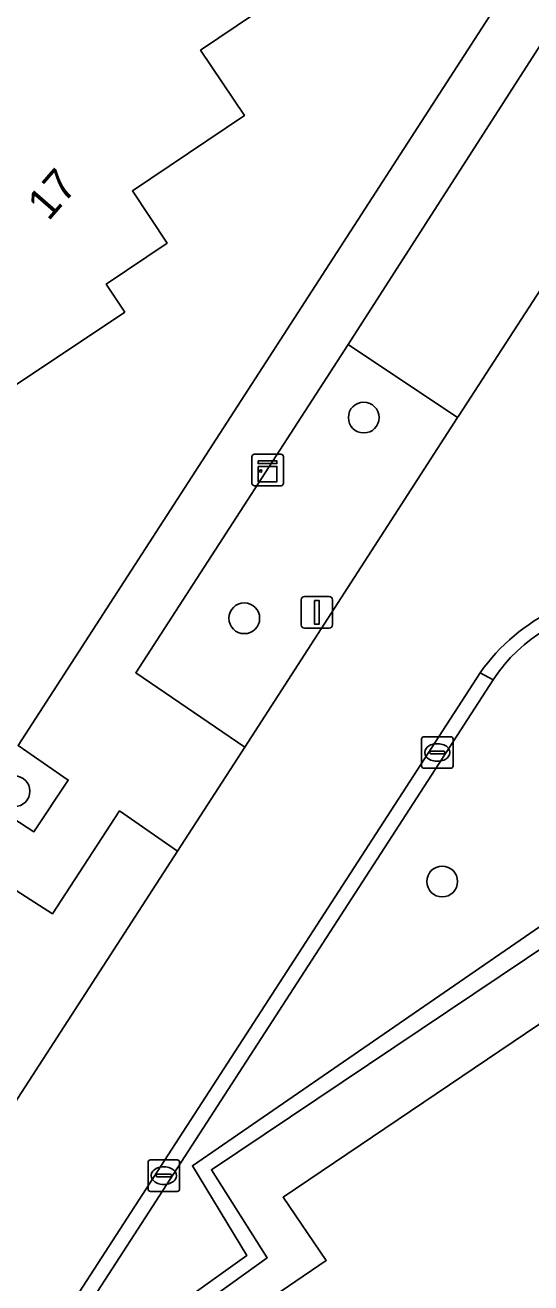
# Model space of a CAD drawing. Extents: x 158793 to 159888, y 384317 to 385256.
# Drawn here: x 158897.57 to 158913.64, y 384644.03 to 384684.03 of the extents above; entities that cross this region are included whole.
import ezdxf

# ---------------------------------------------------------------- set-up
doc = ezdxf.new("R2010")
doc.units = 0
for name, color, linetype in [('IMGEO_Berm_groen', 7, 'Continuous'), ('IMGEO_Boom', 7, 'Continuous'), ('IMGEO_Erf', 7, 'Continuous'), ('IMGEO_Groenvoorziening', 7, 'Continuous'), ('IMGEO_Hek', 7, 'Continuous'), ('IMGEO_Kast', 7, 'Continuous'), ('IMGEO_Kolk', 7, 'Continuous'), ('IMGEO_Lichtmast', 7, 'Continuous'), ('IMGEO_Pand', 7, 'Continuous'), ('IMGEO_Pand_nummerreeks', 7, 'Continuous'), ('IMGEO_Rijbaan_lokaal_open', 7, 'Continuous'), ('IMGEO_Voetpad_open', 7, 'Continuous')]:
    doc.layers.add(name, color=color, linetype=linetype)

msp = doc.modelspace()

# ---------------------------------------------------------------- linework, layer by layer
at = {"layer": 'IMGEO_Berm_groen'}
msp.add_lwpolyline([(158911.309, 384671.553), (158907.828, 384673.873), (158901.084, 384663.437), (158904.546, 384661.066)], close=True, dxfattribs=at)
for points in [[(158912.439, 384663.211), (158898.843, 384642.17)], [(158902.408, 384657.762), (158900.568, 384659.041), (158898.433, 384655.769), (158896.873, 384656.771), (158886.715, 384641.342), (158886.755, 384640.837), (158892.543, 384641.043)], [(158894.078, 384644.875), (158902.408, 384657.762)], [(158914.37, 384620.747), (158915.141, 384621.25), (158911.908, 384626.271), (158911.057, 384625.702), (158910.473, 384626.512), (158909.391, 384625.832), (158899.194, 384641.02), (158904.609, 384644.899), (158902.885, 384647.758), (158917.62, 384657.908)]]:
    msp.add_lwpolyline(points, dxfattribs=at)
msp.add_arc((158916.599, 384660.523), 4.953, 37.5405, 147.1324, dxfattribs=at)
at = {"layer": 'IMGEO_Boom'}
for centre in [(158908.327, 384671.55), (158904.531, 384665.168), (158897.232, 384659.668), (158910.819, 384656.796)]:
    msp.add_circle(centre, 0.489, dxfattribs=at)
at = {"layer": 'IMGEO_Erf'}
for points in [[(158891.236, 384680.76), (158895.06, 384683.33), (158895.28, 384683.003), (158900.155, 384686.29), (158898.829, 384688.27), (158901.189, 384689.866), (158904.892, 384684.406), (158903.142, 384683.233), (158904.534, 384681.155), (158900.976, 384678.758), (158902.078, 384677.102), (158900.144, 384675.796), (158900.734, 384674.905), (158896.946, 384672.367)], [(158935.269, 384640.755), (158935.742, 384641.055), (158931.239, 384647.707), (158930.053, 384646.895), (158926.376, 384644.46), (158920.02, 384653.654), (158917.65, 384657.141), (158903.486, 384647.632), (158905.26, 384644.832), (158899.805, 384640.906), (158909.685, 384626.219), (158910.802, 384626.858), (158911.256, 384626.177), (158922.042, 384633.454), (158922.226, 384633.163), (158925.099, 384628.623), (158936.517, 384636.347), (158935.783, 384637.416), (158937.012, 384638.256)]]:
    msp.add_lwpolyline(points, close=True, dxfattribs=at)
for points in [[(158896.259, 384659.409), (158897.847, 384658.378), (158898.939, 384660.023), (158897.345, 384661.12), (158912.641, 384684.801)], [(158904.737, 384643.112), (158907.129, 384644.742), (158905.762, 384646.758), (158914.28, 384652.511), (158916.47, 384649.231), (158919.852, 384651.521), (158922.28, 384647.917), (158924.575, 384644.51), (158926.138, 384642.19), (158930.948, 384645.466), (158934.462, 384640.251)]]:
    msp.add_lwpolyline(points, dxfattribs=at)
at = {"layer": 'IMGEO_Groenvoorziening'}
msp.add_lwpolyline([(158917.65, 384657.141), (158917.963, 384657.364), (158917.62, 384657.908), (158902.885, 384647.758), (158904.609, 384644.899), (158899.194, 384641.02), (158909.391, 384625.832), (158910.473, 384626.512), (158911.057, 384625.702), (158911.908, 384626.271), (158922.226, 384633.163), (158922.042, 384633.454), (158911.256, 384626.177), (158910.802, 384626.858), (158909.685, 384626.219), (158899.805, 384640.906), (158905.26, 384644.832), (158903.486, 384647.632)], close=True, dxfattribs=at)
at = {"layer": 'IMGEO_Hek'}
for points in [[(158918.924, 384652.902), (158920.02, 384653.654), (158917.65, 384657.141), (158903.486, 384647.632), (158905.26, 384644.832)], [(158905.26, 384644.832), (158899.805, 384640.906), (158909.685, 384626.219), (158910.802, 384626.858), (158911.256, 384626.177), (158922.042, 384633.454), (158922.226, 384633.163), (158925.099, 384628.623), (158936.517, 384636.347), (158935.783, 384637.416)]]:
    msp.add_lwpolyline(points, dxfattribs=at)
at = {"layer": 'IMGEO_Kast'}
for p, q in [((158904.775, 384669.458), (158904.775, 384670.299)), ((158904.775, 384670.299), (158904.775, 384669.458)), ((158904.85, 384670.383), (158905.691, 384670.383)), ((158905.691, 384670.383), (158904.85, 384670.383)), ((158905.775, 384670.308), (158905.775, 384669.467)), ((158905.775, 384669.467), (158905.775, 384670.308)), ((158905.7, 384669.383), (158904.859, 384669.383)), ((158904.859, 384669.383), (158905.7, 384669.383))]:
    msp.add_line(p, q, dxfattribs=at)
for points in [[(158904.97, 384670.173), (158905.57, 384670.173), (158905.57, 384670.088), (158904.97, 384670.088), (158904.97, 384670.173)], [(158904.97, 384669.998), (158905.57, 384669.998), (158905.57, 384669.509), (158904.97, 384669.509), (158904.97, 384669.998)]]:
    msp.add_lwpolyline(points, dxfattribs=at)
msp.add_circle((158905.054, 384669.847), 0.0377, dxfattribs=at)
for centre, start, end in [((158904.853, 384670.305), 92.4484, 184.2845), ((158904.853, 384670.305), 92.4484, 184.2845), ((158905.697, 384670.305), 2.4484, 94.2845), ((158905.697, 384670.305), 2.4484, 94.2845), ((158904.853, 384669.461), 182.4484, 274.2845), ((158904.853, 384669.461), 182.4484, 274.2845), ((158905.697, 384669.461), 272.4484, 4.2845), ((158905.697, 384669.461), 272.4484, 4.2845)]:
    msp.add_arc(centre, 0.0779, start, end, dxfattribs=at)
at = {"layer": 'IMGEO_Kolk'}
for p, q in [((158910.164, 384660.474), (158910.164, 384661.326)), ((158910.239, 384661.4), (158911.091, 384661.4)), ((158911.165, 384661.326), (158911.165, 384660.474)), ((158910.466, 384660.943), (158910.864, 384660.943)), ((158910.652, 384661.18), (158910.677, 384661.18)), ((158910.423, 384660.894), (158910.423, 384660.906)), ((158910.861, 384660.857), (158910.463, 384660.857)), ((158910.675, 384660.62), (158910.65, 384660.62)), ((158910.907, 384660.906), (158910.907, 384660.894)), ((158911.091, 384660.4), (158910.239, 384660.4)), ((158901.475, 384647.017), (158901.475, 384647.869)), ((158901.55, 384647.943), (158902.402, 384647.943)), ((158902.476, 384647.869), (158902.476, 384647.017)), ((158901.734, 384647.437), (158901.734, 384647.449)), ((158902.172, 384647.4), (158901.774, 384647.4)), ((158901.777, 384647.486), (158902.175, 384647.486)), ((158901.963, 384647.723), (158901.988, 384647.723)), ((158902.218, 384647.449), (158902.218, 384647.437)), ((158902.402, 384646.943), (158901.55, 384646.943)), ((158901.986, 384647.163), (158901.961, 384647.163))]:
    msp.add_line(p, q, dxfattribs=at)
for points in [[(158910.164, 384660.474), (158910.164, 384661.326)], [(158910.239, 384661.4), (158911.091, 384661.4)], [(158911.165, 384661.326), (158911.165, 384660.474)], [(158911.091, 384660.4), (158910.239, 384660.4)], [(158901.475, 384647.017), (158901.475, 384647.869)], [(158901.55, 384647.943), (158902.402, 384647.943)], [(158902.476, 384647.869), (158902.476, 384647.017)], [(158902.402, 384646.943), (158901.55, 384646.943)]]:
    msp.add_lwpolyline(points, dxfattribs=at)
for centre, radius, start, end in [((158910.241, 384661.324), 0.0765, 91.552, 178.448), ((158910.241, 384661.324), 0.0765, 91.552, 178.448), ((158911.089, 384661.324), 0.0765, 1.552, 88.448), ((158911.089, 384661.324), 0.0765, 1.552, 88.448), ((158910.463, 384660.903), 0.0403, 85.8775, 175.7526), ((158910.868, 384660.905), 0.0386, 1.7309, 96.639), ((158910.46, 384660.893), 0.0366, 178.938, 274.7102), ((158910.864, 384660.9), 0.043, 264.8664, 352.4533), ((158910.241, 384660.476), 0.0765, 181.552, 268.448), ((158910.241, 384660.476), 0.0765, 181.552, 268.448), ((158911.089, 384660.476), 0.0765, 271.552, 358.448), ((158911.089, 384660.476), 0.0765, 271.552, 358.448), ((158901.552, 384647.867), 0.0765, 91.552, 178.448), ((158901.552, 384647.867), 0.0765, 91.552, 178.448), ((158902.4, 384647.867), 0.0765, 1.552, 88.448), ((158902.4, 384647.867), 0.0765, 1.552, 88.448), ((158901.774, 384647.446), 0.0403, 85.8775, 175.7526), ((158901.771, 384647.436), 0.0366, 178.938, 274.7102), ((158902.175, 384647.443), 0.043, 264.8664, 352.4533), ((158902.179, 384647.448), 0.0386, 1.7309, 96.639), ((158901.552, 384647.019), 0.0765, 181.552, 268.448), ((158901.552, 384647.019), 0.0765, 181.552, 268.448), ((158902.4, 384647.019), 0.0765, 271.552, 358.448), ((158902.4, 384647.019), 0.0765, 271.552, 358.448)]:
    msp.add_arc(centre, radius, start, end, dxfattribs=at)
for centre, major_axis, ratio, start_param, end_param in [((158910.651, 384660.9), (-0.387, 0.002), 0.722429, 4.712389, 7.853982), ((158910.676, 384660.9), (-0.39, 0.002), 0.717154, 1.570796, 4.712389), ((158901.962, 384647.443), (-0.387, 0.002), 0.722429, 4.712389, 7.853982), ((158901.987, 384647.443), (-0.39, 0.002), 0.717154, 1.570796, 4.712389)]:
    msp.add_ellipse(centre, major_axis=major_axis, ratio=ratio, start_param=start_param, end_param=end_param, dxfattribs=at)
at = {"layer": 'IMGEO_Lichtmast'}
for p, q in [((158906.342, 384664.958), (158906.342, 384665.758)), ((158906.342, 384665.758), (158906.342, 384664.958)), ((158906.442, 384665.858), (158907.232, 384665.858)), ((158907.232, 384665.858), (158906.442, 384665.858)), ((158907.332, 384665.758), (158907.332, 384664.958)), ((158907.332, 384664.958), (158907.332, 384665.758)), ((158907.232, 384664.858), (158906.442, 384664.858)), ((158906.442, 384664.858), (158907.232, 384664.858))]:
    msp.add_line(p, q, dxfattribs=at)
msp.add_lwpolyline([(158906.762, 384665.733), (158906.912, 384665.733), (158906.912, 384664.983), (158906.762, 384664.983), (158906.762, 384665.733)], dxfattribs=at)
for centre, start, end in [((158906.442, 384665.758), 90, 180), ((158906.442, 384665.758), 90, 180), ((158907.232, 384665.758), 0, 90), ((158907.232, 384665.758), 360, 90), ((158906.442, 384664.958), 180, 270), ((158906.442, 384664.958), 180, 270), ((158907.232, 384664.958), 270, 0), ((158907.232, 384664.958), 270, 0)]:
    msp.add_arc(centre, 0.1, start, end, dxfattribs=at)
at = {"layer": 'IMGEO_Pand'}
for points in [[(158891.236, 384680.76), (158896.946, 384672.367), (158900.734, 384674.905), (158900.144, 384675.796), (158902.078, 384677.102), (158900.976, 384678.758), (158904.534, 384681.155), (158903.142, 384683.233), (158904.892, 384684.406), (158901.189, 384689.866), (158898.829, 384688.27), (158900.155, 384686.29), (158895.28, 384683.003), (158895.06, 384683.33)], [(158922.28, 384647.917), (158919.852, 384651.521), (158916.47, 384649.231), (158914.28, 384652.511), (158905.762, 384646.758), (158907.129, 384644.742), (158904.737, 384643.112), (158907.976, 384638.304)]]:
    msp.add_lwpolyline(points, close=True, dxfattribs=at)
at = {"layer": 'IMGEO_Rijbaan_lokaal_open'}
for points in [[(158920.897, 384677.203), (158925.966, 384685.017), (158921.775, 384687.75), (158917.772, 384681.542), (158911.358, 384671.629), (158911.309, 384671.553), (158904.546, 384661.066), (158902.408, 384657.762), (158894.078, 384644.875)], [(158912.439, 384663.211), (158912.025, 384663.435), (158898.456, 384642.456)], [(158898.456, 384642.456), (158912.025, 384663.435)], [(158912.025, 384663.435), (158912.439, 384663.211)], [(158898.843, 384642.17), (158912.439, 384663.211)]]:
    msp.add_lwpolyline(points, dxfattribs=at)
for centre, radius, start, end in [((158917.078, 384659.881), 6.178, 115.1979, 144.8814), ((158917.078, 384659.881), 6.178, 115.1979, 144.8814), ((158916.599, 384660.523), 4.953, 37.5405, 147.1324)]:
    msp.add_arc(centre, radius, start, end, dxfattribs=at)
at = {"layer": 'IMGEO_Voetpad_open'}
for points in [[(158903.319, 384612.632), (158899.607, 384618.157), (158887.623, 384636.03), (158887.066, 384636.861), (158886.755, 384640.837), (158886.715, 384641.342), (158896.873, 384656.771), (158898.433, 384655.769), (158900.568, 384659.041), (158902.408, 384657.762), (158904.546, 384661.066), (158901.084, 384663.437), (158907.828, 384673.873), (158914.233, 384683.849), (158920.408, 384693.282)], [(158912.641, 384684.801), (158897.345, 384661.12), (158898.939, 384660.023), (158897.847, 384658.378), (158896.259, 384659.409), (158883.161, 384639.419), (158898.058, 384617.173)]]:
    msp.add_lwpolyline(points, dxfattribs=at)
msp.add_lwpolyline([(158917.772, 384681.542), (158914.233, 384683.849), (158907.828, 384673.873), (158911.309, 384671.553), (158911.358, 384671.629)], close=True, dxfattribs=at)

# ---------------------------------------------------------------- texts
at = {"layer": 'IMGEO_Pand_nummerreeks'}
msp.add_text('17', height=1, rotation=49.0084, dxfattribs=at).set_placement((158898.311, 384677.773))

doc.saveas('drawing.dxf')
